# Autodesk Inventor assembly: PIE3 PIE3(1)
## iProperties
Shininess: 64.0
Length Units: 11269
Angle Units: 11279
Time Units: 11290
Mass Units: 11286
Length Display Precision: 3
Angle Display Precision: 2
Compacted: True
Part Number: PIE3 PIE3(1)
Document SubType Name: Assembly
Created: 2004-08
Designer: John Blackburn
Manufacturer: Standard
Standards Organization: Custom
Density: 0.0
Volumn: 0.0
Area: 0.0
PropertySet Name: Model Information
Control State: 0
Master: False
Checked Out: False
Author: John Blackburn
